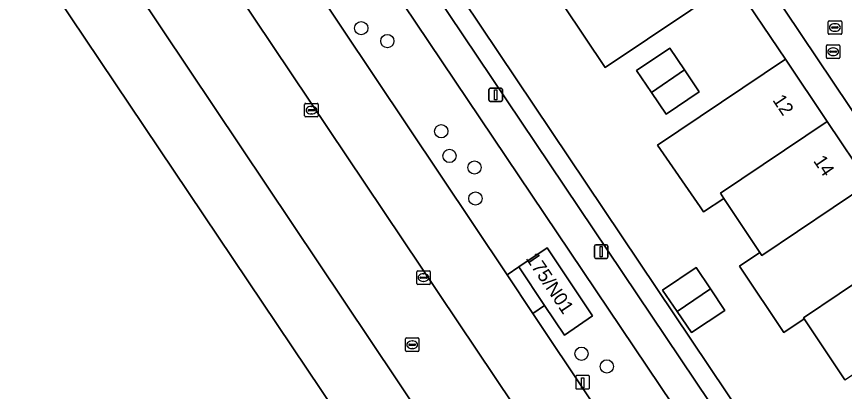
# Model space of a CAD drawing. Extents: x 158793 to 159888, y 384317 to 385256.
# Drawn here: x 159071.1 to 159132.2, y 384501.3 to 384528.9 of the extents above; entities that cross this region are included whole.
import ezdxf

# ---------------------------------------------------------------- set-up
doc = ezdxf.new("R2010")
doc.units = 0
for name, color, linetype in [('IMGEO_Boom', 7, 'Continuous'), ('IMGEO_Erf', 7, 'Continuous'), ('IMGEO_Groenvoorziening', 7, 'Continuous'), ('IMGEO_Kolk', 7, 'Continuous'), ('IMGEO_Laadpaal', 7, 'Continuous'), ('IMGEO_Lichtmast', 7, 'Continuous'), ('IMGEO_Pand', 7, 'Continuous'), ('IMGEO_Pand_nummerreeks', 7, 'Continuous'), ('IMGEO_Parkeervlak_open', 7, 'Continuous'), ('IMGEO_Rijbaan_lokaal_open', 7, 'Continuous'), ('IMGEO_Rioolput', 7, 'Continuous'), ('IMGEO_Voetpad_open', 7, 'Continuous')]:
    doc.layers.add(name, color=color, linetype=linetype)

msp = doc.modelspace()

# ---------------------------------------------------------------- linework, layer by layer
at = {"layer": 'IMGEO_Boom'}
for centre in [(159096.504, 384528.079), (159098.43, 384527.126), (159102.409, 384520.471), (159103.014, 384518.651), (159104.865, 384517.798), (159104.93, 384515.512), (159112.752, 384504.056), (159114.623, 384503.12)]:
    msp.add_circle(centre, 0.489, dxfattribs=at)
at = {"layer": 'IMGEO_Erf'}
for points in [[(159092.403, 384547.537), (159146.803, 384466.42)], [(159132.189, 384502.119), (159129.183, 384506.629), (159127.677, 384505.625), (159127.631, 384505.694), (159124.565, 384510.295), (159124.416, 384510.518), (159125.922, 384511.522), (159123.26, 384515.516), (159121.762, 384514.518), (159121.501, 384514.897), (159118.368, 384519.453), (159127.802, 384525.792), (159123.956, 384531.511), (159114.509, 384525.165), (159111.442, 384529.73)]]:
    msp.add_lwpolyline(points, dxfattribs=at)
for points in [[(159118.994, 384521.72), (159117.91, 384523.327), (159116.822, 384524.941), (159119.268, 384526.601), (159120.354, 384524.991), (159121.441, 384523.38)], [(159123.325, 384507.255), (159120.863, 384505.615), (159119.812, 384507.166), (159118.745, 384508.741), (159121.221, 384510.427), (159122.273, 384508.841)]]:
    msp.add_lwpolyline(points, close=True, dxfattribs=at)
at = {"layer": 'IMGEO_Groenvoorziening'}
for points in [[(159091.171, 384546.721), (159089.196, 384545.377), (159129.89, 384484.816), (159131.847, 384486.145)], [(159089.196, 384545.377), (159085.318, 384542.737), (159107.263, 384509.883), (159108.122, 384510.457), (159110.211, 384511.86), (159113.576, 384506.843), (159111.49, 384505.432), (159110.027, 384507.615), (159109.176, 384507.019), (159125.843, 384482.068), (159129.89, 384484.816)]]:
    msp.add_lwpolyline(points, close=True, dxfattribs=at)
at = {"layer": 'IMGEO_Kolk'}
for p, q in [((159092.329, 384521.603), (159092.329, 384522.455)), ((159092.404, 384522.529), (159093.256, 384522.529)), ((159092.588, 384522.023), (159092.588, 384522.035)), ((159093.026, 384521.986), (159092.628, 384521.986)), ((159092.631, 384522.072), (159093.029, 384522.072)), ((159092.817, 384522.309), (159092.842, 384522.309)), ((159093.072, 384522.035), (159093.072, 384522.023)), ((159093.33, 384522.455), (159093.33, 384521.603)), ((159093.256, 384521.529), (159092.404, 384521.529)), ((159092.84, 384521.749), (159092.815, 384521.749)), ((159100.6, 384509.247), (159100.6, 384510.099)), ((159100.675, 384510.173), (159101.527, 384510.173)), ((159100.902, 384509.716), (159101.3, 384509.716)), ((159101.088, 384509.953), (159101.113, 384509.953)), ((159101.601, 384510.099), (159101.601, 384509.247)), ((159101.527, 384509.173), (159100.675, 384509.173)), ((159100.859, 384509.667), (159100.859, 384509.679)), ((159101.297, 384509.63), (159100.899, 384509.63)), ((159101.111, 384509.393), (159101.086, 384509.393)), ((159101.343, 384509.679), (159101.343, 384509.667))]:
    msp.add_line(p, q, dxfattribs=at)
for points in [[(159092.329, 384521.603), (159092.329, 384522.455)], [(159092.404, 384522.529), (159093.256, 384522.529)], [(159093.33, 384522.455), (159093.33, 384521.603)], [(159093.256, 384521.529), (159092.404, 384521.529)], [(159100.6, 384509.247), (159100.6, 384510.099)], [(159100.675, 384510.173), (159101.527, 384510.173)], [(159101.601, 384510.099), (159101.601, 384509.247)], [(159101.527, 384509.173), (159100.675, 384509.173)]]:
    msp.add_lwpolyline(points, dxfattribs=at)
for centre, radius, start, end in [((159092.406, 384522.453), 0.0765, 91.55205, 178.44795), ((159092.406, 384522.453), 0.0765, 91.55205, 178.44795), ((159092.628, 384522.032), 0.0403, 85.87752, 175.75265), ((159092.625, 384522.022), 0.0366, 178.93798, 274.71019), ((159093.029, 384522.029), 0.043, 264.86636, 352.45326), ((159093.033, 384522.034), 0.0386, 1.73085, 96.63898), ((159093.254, 384522.453), 0.0765, 1.55205, 88.44795), ((159093.254, 384522.453), 0.0765, 1.55205, 88.44795), ((159092.406, 384521.605), 0.0765, 181.55205, 268.44795), ((159092.406, 384521.605), 0.0765, 181.55205, 268.44795), ((159093.254, 384521.605), 0.0765, 271.55205, 358.44795), ((159093.254, 384521.605), 0.0765, 271.55205, 358.44795), ((159100.677, 384510.097), 0.0765, 91.55205, 178.44795), ((159100.677, 384510.097), 0.0765, 91.55205, 178.44795), ((159100.899, 384509.676), 0.0403, 85.87752, 175.75265), ((159101.304, 384509.678), 0.0386, 1.73085, 96.63898), ((159101.525, 384510.097), 0.0765, 1.55205, 88.44795), ((159101.525, 384510.097), 0.0765, 1.55205, 88.44795), ((159100.677, 384509.249), 0.0765, 181.55205, 268.44795), ((159100.677, 384509.249), 0.0765, 181.55205, 268.44795), ((159100.896, 384509.666), 0.0366, 178.93798, 274.71019), ((159101.3, 384509.673), 0.043, 264.86636, 352.45326), ((159101.525, 384509.249), 0.0765, 271.55205, 358.44795), ((159101.525, 384509.249), 0.0765, 271.55205, 358.44795)]:
    msp.add_arc(centre, radius, start, end, dxfattribs=at)
for centre, major_axis, ratio, start_param, end_param in [((159092.816, 384522.029), (-0.387, 0.002), 0.722429, 4.712389, 7.853982), ((159092.841, 384522.029), (-0.39, 0.002), 0.717154, 1.570796, 4.712389), ((159101.087, 384509.673), (-0.387, 0.002), 0.722429, 4.712389, 7.853982), ((159101.112, 384509.673), (-0.39, 0.002), 0.717154, 1.570796, 4.712389)]:
    msp.add_ellipse(centre, major_axis=major_axis, ratio=ratio, start_param=start_param, end_param=end_param, dxfattribs=at)
at = {"layer": 'IMGEO_Laadpaal'}
for p, q in [((159113.257, 384502.457), (159112.416, 384502.457)), ((159113.257, 384502.457), (159112.416, 384502.457)), ((159112.341, 384502.373), (159112.341, 384501.532)), ((159112.341, 384502.373), (159112.341, 384501.532)), ((159113.341, 384501.541), (159113.341, 384502.382)), ((159113.341, 384501.541), (159113.341, 384502.382)), ((159112.425, 384501.457), (159113.266, 384501.457)), ((159112.425, 384501.457), (159113.266, 384501.457))]:
    msp.add_line(p, q, dxfattribs=at)
msp.add_lwpolyline([(159112.756, 384502.27), (159112.916, 384502.27), (159112.916, 384501.537), (159112.756, 384501.537), (159112.756, 384502.27)], dxfattribs=at)
for centre, start, end in [((159112.419, 384502.379), 92.4484, 184.28452), ((159112.419, 384502.379), 92.4484, 184.28452), ((159113.263, 384502.379), 2.4484, 94.28452), ((159113.263, 384502.379), 2.4484, 94.28452), ((159112.419, 384501.535), 182.4484, 274.28452), ((159112.419, 384501.535), 182.4484, 274.28452), ((159113.263, 384501.535), 272.4484, 4.28452), ((159113.263, 384501.535), 272.4484, 4.28452)]:
    msp.add_arc(centre, 0.0779, start, end, dxfattribs=at)
at = {"layer": 'IMGEO_Lichtmast'}
for p, q in [((159105.927, 384522.757), (159105.927, 384523.557)), ((159105.927, 384523.557), (159105.927, 384522.757)), ((159106.027, 384523.657), (159106.817, 384523.657)), ((159106.817, 384523.657), (159106.027, 384523.657)), ((159106.917, 384523.557), (159106.917, 384522.757)), ((159106.917, 384522.757), (159106.917, 384523.557)), ((159106.817, 384522.657), (159106.027, 384522.657)), ((159106.027, 384522.657), (159106.817, 384522.657)), ((159113.721, 384511.193), (159113.721, 384511.993)), ((159113.721, 384511.993), (159113.721, 384511.193)), ((159113.821, 384512.093), (159114.611, 384512.093)), ((159114.611, 384512.093), (159113.821, 384512.093)), ((159114.711, 384511.993), (159114.711, 384511.193)), ((159114.711, 384511.193), (159114.711, 384511.993)), ((159114.611, 384511.093), (159113.821, 384511.093)), ((159113.821, 384511.093), (159114.611, 384511.093))]:
    msp.add_line(p, q, dxfattribs=at)
for points in [[(159106.347, 384523.532), (159106.497, 384523.532), (159106.497, 384522.782), (159106.347, 384522.782), (159106.347, 384523.532)], [(159114.141, 384511.968), (159114.291, 384511.968), (159114.291, 384511.218), (159114.141, 384511.218), (159114.141, 384511.968)]]:
    msp.add_lwpolyline(points, dxfattribs=at)
for centre, start, end in [((159106.027, 384523.557), 90, 180), ((159106.027, 384523.557), 90, 180), ((159106.817, 384523.557), 0, 90), ((159106.817, 384523.557), 360, 90), ((159106.027, 384522.757), 180, 270), ((159106.027, 384522.757), 180, 270), ((159106.817, 384522.757), 270, 0), ((159106.817, 384522.757), 270, 0), ((159113.821, 384511.993), 90, 180), ((159113.821, 384511.993), 90, 180), ((159114.611, 384511.993), 0, 90), ((159114.611, 384511.993), 360, 90), ((159113.821, 384511.193), 180, 270), ((159113.821, 384511.193), 180, 270), ((159114.611, 384511.193), 270, 0), ((159114.611, 384511.193), 270, 0)]:
    msp.add_arc(centre, 0.1, start, end, dxfattribs=at)
at = {"layer": 'IMGEO_Pand'}
for points in [[(159123.956, 384531.511), (159120.886, 384536.081), (159112.944, 384530.74), (159112.722, 384531.071), (159111.219, 384530.062), (159111.442, 384529.73), (159114.509, 384525.165)], [(159071.774, 384533.799), (159050.67, 384519.624), (159058.757, 384507.518), (159100.592, 384444.894), (159099.734, 384444.322), (159105.622, 384435.536), (159134.297, 384454.798), (159140.265, 384458.806), (159139.961, 384459.26), (159139.482, 384459.974), (159134.495, 384467.411), (159134.397, 384467.557), (159129.91, 384464.543), (159126.029, 384461.936), (159121.905, 384459.166)], [(159119.268, 384526.601), (159116.822, 384524.941), (159117.91, 384523.327), (159120.354, 384524.991)], [(159130.881, 384521.199), (159127.802, 384525.792), (159118.368, 384519.453), (159121.501, 384514.897), (159121.762, 384514.518), (159123.26, 384515.516), (159123.001, 384515.905)], [(159120.354, 384524.991), (159117.91, 384523.327), (159118.994, 384521.72), (159121.441, 384523.38)], [(159133.961, 384516.607), (159130.881, 384521.199), (159123.001, 384515.905), (159123.26, 384515.516), (159125.922, 384511.522), (159126.067, 384511.304)], [(159137.04, 384512.015), (159133.961, 384516.607), (159126.067, 384511.304), (159125.922, 384511.522), (159124.416, 384510.518), (159124.565, 384510.295), (159127.631, 384505.694), (159127.677, 384505.625), (159129.183, 384506.629), (159129.133, 384506.703)], [(159110.211, 384511.86), (159108.122, 384510.457), (159110.027, 384507.615), (159111.49, 384505.432), (159113.576, 384506.843)], [(159140.119, 384507.423), (159137.04, 384512.015), (159129.133, 384506.703), (159129.183, 384506.629), (159132.189, 384502.119)], [(159118.745, 384508.741), (159119.812, 384507.166), (159122.273, 384508.841), (159121.221, 384510.427)], [(159122.273, 384508.841), (159119.812, 384507.166), (159120.863, 384505.615), (159123.325, 384507.255)]]:
    msp.add_lwpolyline(points, close=True, dxfattribs=at)
at = {"layer": 'IMGEO_Parkeervlak_open'}
msp.add_lwpolyline([(159085.318, 384542.737), (159081.166, 384539.91), (159081.78, 384538.994), (159114.556, 384490.118), (159121.763, 384479.19), (159125.843, 384482.068), (159109.176, 384507.019), (159107.263, 384509.883)], close=True, dxfattribs=at)
at = {"layer": 'IMGEO_Rijbaan_lokaal_open'}
for points in [[(159211.83, 384541.696), (159201.909, 384535.023), (159197.999, 384532.399), (159196.883, 384531.677), (159196.033, 384531.127), (159195.59, 384530.821), (159178.371, 384556.579), (159178.788, 384556.84), (159178.669, 384557.017), (159179.615, 384557.65), (159184.571, 384560.964), (159188.261, 384563.455), (159191.903, 384565.914), (159196.883, 384569.224), (159195.001, 384572.021), (159178.017, 384560.678), (159131.797, 384529.704), (159111.782, 384559.411), (159108.917, 384557.49), (159163.183, 384476.655), (159166.119, 384478.572), (159153.048, 384498.068), (159198.654, 384528.669), (159243.562, 384558.734)], [(159131.847, 384486.145), (159129.89, 384484.816), (159125.843, 384482.068), (159121.763, 384479.19), (159114.556, 384490.118), (159081.78, 384538.994), (159081.166, 384539.91), (159076.06, 384536.619), (159126.029, 384461.936), (159129.91, 384464.543), (159134.397, 384467.557), (159134.495, 384467.411), (159137.367, 384469.377), (159142.448, 384461.963), (159142.934, 384461.253), (159146.329, 384456.299), (159147.152, 384455.106), (159151.122, 384449.331), (159151.815, 384448.322), (159153.174, 384446.346)]]:
    msp.add_lwpolyline(points, dxfattribs=at)
at = {"layer": 'IMGEO_Rioolput'}
for p, q in [((159130.953, 384527.697), (159130.953, 384528.549)), ((159131.028, 384528.623), (159131.88, 384528.623)), ((159131.212, 384528.117), (159131.212, 384528.129)), ((159131.65, 384528.08), (159131.252, 384528.08)), ((159131.255, 384528.166), (159131.653, 384528.166)), ((159131.441, 384528.403), (159131.466, 384528.403)), ((159131.696, 384528.129), (159131.696, 384528.117)), ((159131.954, 384528.549), (159131.954, 384527.697)), ((159131.88, 384527.623), (159131.028, 384527.623)), ((159131.464, 384527.843), (159131.439, 384527.843)), ((159130.898, 384526.838), (159131.75, 384526.838)), ((159130.823, 384525.912), (159130.823, 384526.764)), ((159131.082, 384526.332), (159131.082, 384526.344)), ((159131.52, 384526.295), (159131.122, 384526.295)), ((159131.125, 384526.381), (159131.523, 384526.381)), ((159131.311, 384526.618), (159131.336, 384526.618)), ((159131.566, 384526.344), (159131.566, 384526.332)), ((159131.824, 384526.764), (159131.824, 384525.912)), ((159131.75, 384525.838), (159130.898, 384525.838)), ((159131.334, 384526.058), (159131.309, 384526.058)), ((159099.764, 384504.293), (159099.764, 384505.145)), ((159099.839, 384505.219), (159100.691, 384505.219)), ((159100.252, 384504.999), (159100.277, 384504.999)), ((159100.765, 384505.145), (159100.765, 384504.293)), ((159100.691, 384504.219), (159099.839, 384504.219)), ((159100.023, 384504.713), (159100.023, 384504.725)), ((159100.461, 384504.676), (159100.063, 384504.676)), ((159100.066, 384504.762), (159100.464, 384504.762)), ((159100.275, 384504.439), (159100.25, 384504.439)), ((159100.507, 384504.725), (159100.507, 384504.713))]:
    msp.add_line(p, q, dxfattribs=at)
for points in [[(159130.953, 384527.697), (159130.953, 384528.549)], [(159131.028, 384528.623), (159131.88, 384528.623)], [(159131.954, 384528.549), (159131.954, 384527.697)], [(159131.88, 384527.623), (159131.028, 384527.623)], [(159130.898, 384526.838), (159131.75, 384526.838)], [(159130.823, 384525.912), (159130.823, 384526.764)], [(159131.824, 384526.764), (159131.824, 384525.912)], [(159131.75, 384525.838), (159130.898, 384525.838)], [(159099.764, 384504.293), (159099.764, 384505.145)], [(159099.839, 384505.219), (159100.691, 384505.219)], [(159100.765, 384505.145), (159100.765, 384504.293)], [(159100.691, 384504.219), (159099.839, 384504.219)]]:
    msp.add_lwpolyline(points, dxfattribs=at)
for centre, radius, start, end in [((159131.03, 384528.547), 0.0765, 91.55205, 178.44795), ((159131.03, 384528.547), 0.0765, 91.55205, 178.44795), ((159131.252, 384528.126), 0.0403, 85.87752, 175.75265), ((159131.249, 384528.116), 0.0366, 178.93798, 274.71019), ((159131.653, 384528.123), 0.043, 264.86636, 352.45326), ((159131.657, 384528.128), 0.0386, 1.73085, 96.63898), ((159131.878, 384528.547), 0.0765, 1.55205, 88.44795), ((159131.878, 384528.547), 0.0765, 1.55205, 88.44795), ((159131.03, 384527.699), 0.0765, 181.55205, 268.44795), ((159131.03, 384527.699), 0.0765, 181.55205, 268.44795), ((159131.878, 384527.699), 0.0765, 271.55205, 358.44795), ((159131.878, 384527.699), 0.0765, 271.55205, 358.44795), ((159130.9, 384526.762), 0.0765, 91.55205, 178.44795), ((159130.9, 384526.762), 0.0765, 91.55205, 178.44795), ((159131.748, 384526.762), 0.0765, 1.55205, 88.44795), ((159131.748, 384526.762), 0.0765, 1.55205, 88.44795), ((159131.122, 384526.341), 0.0403, 85.87752, 175.75265), ((159131.119, 384526.331), 0.0366, 178.93798, 274.71019), ((159131.523, 384526.338), 0.043, 264.86636, 352.45326), ((159131.527, 384526.343), 0.0386, 1.73085, 96.63898), ((159130.9, 384525.914), 0.0765, 181.55205, 268.44795), ((159130.9, 384525.914), 0.0765, 181.55205, 268.44795), ((159131.748, 384525.914), 0.0765, 271.55205, 358.44795), ((159131.748, 384525.914), 0.0765, 271.55205, 358.44795), ((159099.841, 384505.143), 0.0765, 91.55205, 178.44795), ((159099.841, 384505.143), 0.0765, 91.55205, 178.44795), ((159100.689, 384505.143), 0.0765, 1.55205, 88.44795), ((159100.689, 384505.143), 0.0765, 1.55205, 88.44795), ((159099.841, 384504.295), 0.0765, 181.55205, 268.44795), ((159099.841, 384504.295), 0.0765, 181.55205, 268.44795), ((159100.063, 384504.722), 0.0403, 85.87752, 175.75265), ((159100.06, 384504.712), 0.0366, 178.93798, 274.71019), ((159100.464, 384504.719), 0.043, 264.86636, 352.45326), ((159100.468, 384504.724), 0.0386, 1.73085, 96.63898), ((159100.689, 384504.295), 0.0765, 271.55205, 358.44795), ((159100.689, 384504.295), 0.0765, 271.55205, 358.44795)]:
    msp.add_arc(centre, radius, start, end, dxfattribs=at)
for centre, major_axis, ratio, start_param, end_param in [((159131.44, 384528.123), (-0.387, 0.002), 0.722429, 4.712389, 7.853982), ((159131.465, 384528.123), (-0.39, 0.002), 0.717154, 1.570796, 4.712389), ((159131.31, 384526.338), (-0.387, 0.002), 0.722429, 4.712389, 7.853982), ((159131.335, 384526.338), (-0.39, 0.002), 0.717154, 1.570796, 4.712389), ((159100.251, 384504.719), (-0.387, 0.002), 0.722429, 4.712389, 7.853982), ((159100.276, 384504.719), (-0.39, 0.002), 0.717154, 1.570796, 4.712389)]:
    msp.add_ellipse(centre, major_axis=major_axis, ratio=ratio, start_param=start_param, end_param=end_param, dxfattribs=at)
at = {"layer": 'IMGEO_Voetpad_open'}
for points in [[(159163.183, 384476.655), (159108.917, 384557.49)], [(159081.017, 384540.159), (159081.037, 384540.102), (159081.166, 384539.91), (159085.318, 384542.737), (159089.196, 384545.377), (159091.171, 384546.721), (159131.847, 384486.145), (159145.592, 384465.604), (159146.046, 384465.91), (159146.803, 384466.42), (159092.403, 384547.537), (159106.711, 384557.186)], [(159106.711, 384557.186), (159108.605, 384554.36), (159111.676, 384549.79), (159114.746, 384545.22), (159117.816, 384540.65), (159120.886, 384536.081), (159123.956, 384531.511), (159127.802, 384525.792), (159130.881, 384521.199), (159133.961, 384516.607)]]:
    msp.add_lwpolyline(points, dxfattribs=at)
for points in [[(159126.029, 384461.936), (159076.06, 384536.619), (159071.774, 384533.799), (159121.905, 384459.166)], [(159108.122, 384510.457), (159107.263, 384509.883), (159109.176, 384507.019), (159110.027, 384507.615)]]:
    msp.add_lwpolyline(points, close=True, dxfattribs=at)

# ---------------------------------------------------------------- texts
at = {"layer": 'IMGEO_Pand_nummerreeks'}
for s, rotation, p in [('12', 303.83868, (159126.817, 384522.772)), ('14', 303.85014, (159129.828, 384518.283)), ('175/N01', 303.83868, (159108.609, 384511.093))]:
    msp.add_text(s, height=1, rotation=rotation, dxfattribs=at).set_placement(p)

doc.saveas('drawing.dxf')
